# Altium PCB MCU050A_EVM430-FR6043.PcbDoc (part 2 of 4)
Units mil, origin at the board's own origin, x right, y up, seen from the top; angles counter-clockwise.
Board outline 6000 x 4000 mil, 4 copper layers (Top Layer, GND, PWR, Bottom Layer), stack 61.2 mil thick; 337 components, 255 nets, 1099 pads, 437 vias.
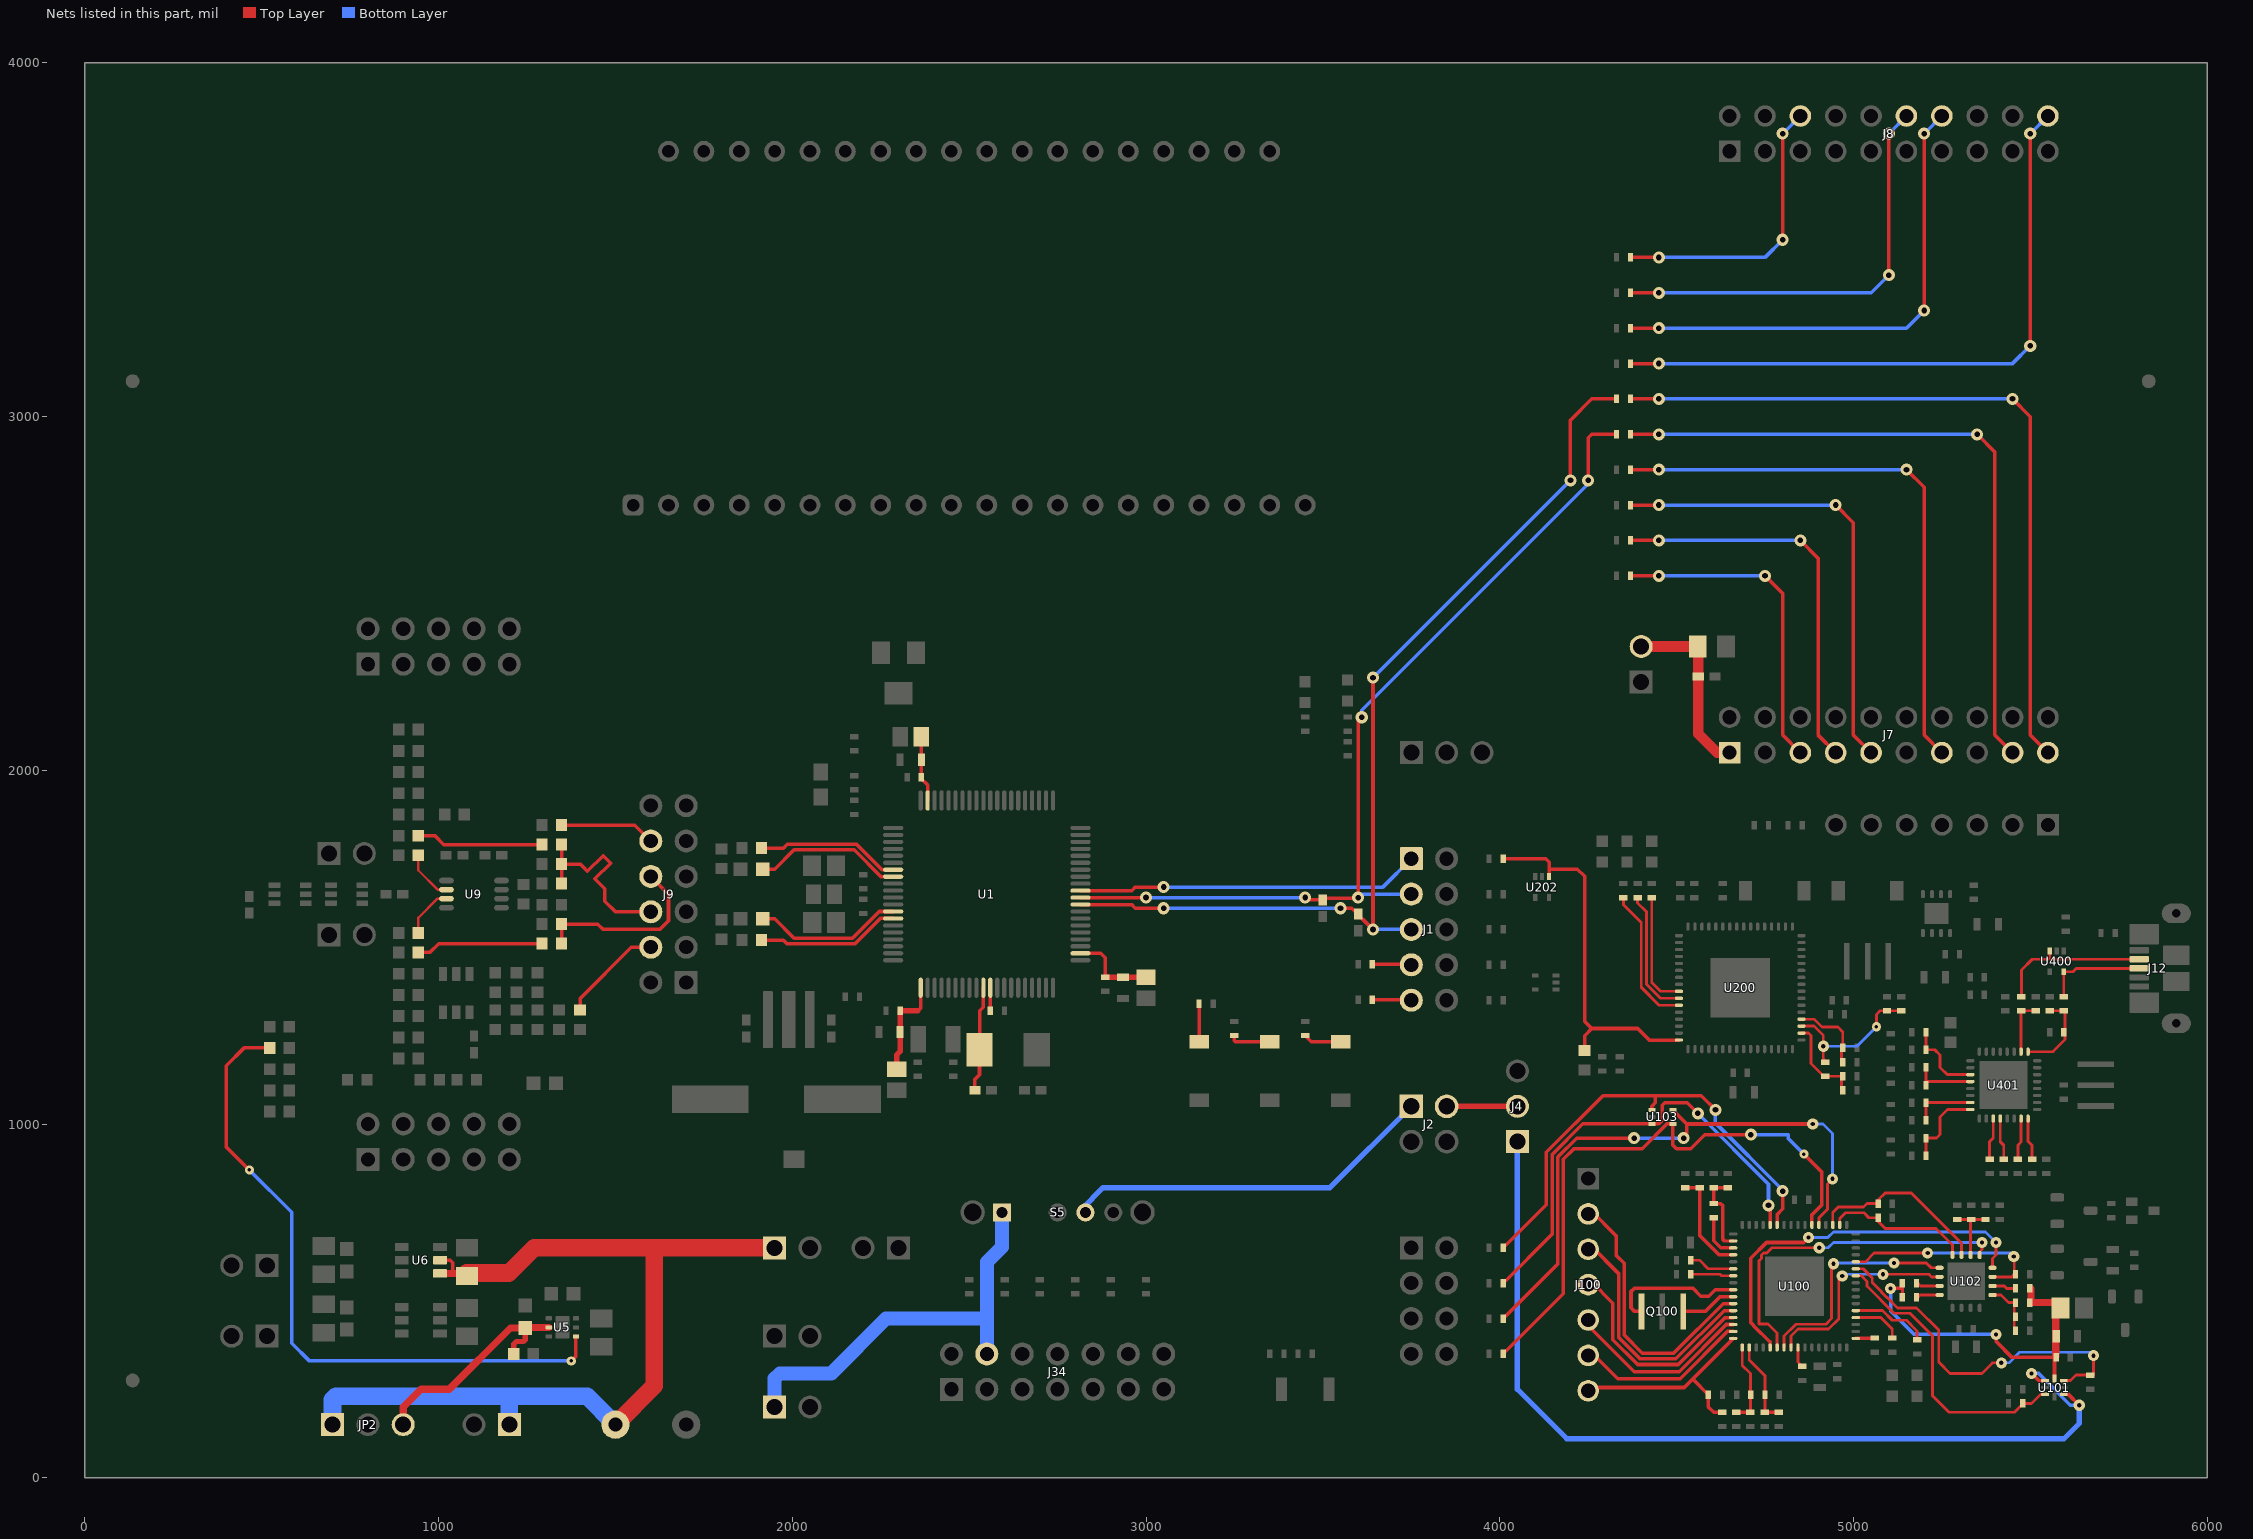
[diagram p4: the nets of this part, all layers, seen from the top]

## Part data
C1 C2 C3 C23 C33 C34 C37 C38 C41 C102 C104 C108 C113 C118 C119 C121 C202 C203 C204 C400 C402 C408 C409 C411: "CAP, CERM, 0.1 µF, 16 V, +/- 10%, X7R, 0402", Cap_Case=0402, Manufacturer=MuRata, Supplier Part Number 1=490-3261-1-ND, TempCo=X7R, Tolerance_%=10, Value1=Unknown, Value2=16V, ValueDisplayed=0.1µF
C4 C5 C17 C111 C210: "CAP, CERM, 1000 pF, 50 V, +/- 5%, C0G/NP0, 0402", Cap_Case=0402, Manufacturer=MuRata, Supplier Part Number 1=490-3244-1-ND, TempCo=C0G/NP0, Tolerance_%=5, Value1=Unknown, Value2=50V, ValueDisplayed=1000pF
C6 C7 C8: "CAP, CERM, 1 µF, 10 V, +/- 10%, X7R, 0603", Cap_Case=0603, Manufacturer=MuRata, Supplier Part Number 1=490-3899-1-ND, TempCo=X7R, Tolerance_%=10, Value1="0.011 ohm", Value2=10V, ValueDisplayed=1µF
C9 C10: library part CMP-0007824-2, "CAP, CERM, 33 uF, 10 V, +/- 20%, X5R, 0805", Cap_Case=0805, Manufacturer=TDK, Supplier Part Number 1=445-8238-1-ND, TempCo=X5R, Tolerance_%=20%, Value1="0.001694 ohm", Value2=10V, ValueDisplayed=33uF
C11 C12 C13 C14 C15 C16: "CAP, CERM, 12 pF, 50 V, +/- 5%, C0G/NP0, 0402", Cap_Case=0402, Manufacturer=MuRata, Supplier Part Number 1=81-GRM1555C1H120JA1D, TempCo=C0G/NP0, Tolerance_%=5, Value1=Unknown, Value2=50V, ValueDisplayed=12pF
C18 C103 C112 C116 C117 C120 C205: "CAP, CERM, 4.7 µF, 10 V, +/- 20%, X5R, 0603", Cap_Case=0603, Manufacturer=MuRata, TempCo=X5R, Tolerance_%=20, Value1=Unknown, Value2=10V, ValueDisplayed=4.7µF
C24: "CAP, CERM, 47 µF, 6.3 V, +/- 20%, X5R, 0805", Cap_Case=0805, Manufacturer=MuRata, Supplier Part Number 1=490-9960-1-ND, TempCo=X5R, Tolerance_%=20, Value1=Unknown, Value2=6.3V, ValueDisplayed=47µF
C25 C30: library part CMP-0008196-2, "CAP, CERM, 10 uF, 10 V, +/- 10%, X5R, 0805", Cap_Case=0805, Manufacturer=MuRata, Supplier Part Number 1=490-4735-1-ND, TempCo=X5R, Tolerance_%=10%, Value1="0.005 ohm", Value2=10V, ValueDisplayed=10uF
C27 C32: library part CMP-0008291-2, "CAP, CERM, 1 uF, 16 V, +/- 10%, X5R, 0805", Cap_Case=0805, Manufacturer=MuRata, Supplier Part Number 1=GRM21BR61C105KA01L-ND, TempCo=X5R, Tolerance_%=10%, Value1=Unknown, Value2=16V, ValueDisplayed=1uF
C28 C35 C45 C46: "CAP, CERM, 2.2 µF, 16 V, +/- 10%, X5R, 0603", Cap_Case=0603, Manufacturer=MuRata, Supplier Part Number 1=490-3296-1-ND, TempCo=X5R, Tolerance_%=10, Value1=Unknown, Value2=16V, ValueDisplayed=2.2µF
C29: "CAP, CERM, 4.7 µF, 16 V, +/- 10%, X5R, 0603", Cap_Case=0603, Manufacturer=MuRata, Supplier Part Number 1=490-10481-1-ND, TempCo=X5R, Tolerance_%=10, Value1=Unknown, Value2=16V, ValueDisplayed=4.7µF
C36 C40 C43: "CAP, CERM, 1 µF, 16 V, +/- 10%, X7R, 0603", Cap_Case=0603, Manufacturer=MuRata, Supplier Part Number 1=490-3900-1-ND, TempCo=X7R, Tolerance_%=10, Value1="0.011 ohm", Value2=16V, ValueDisplayed=1µF
C39: "CAP, CERM, 33 pF, 50 V, +/- 5%, C0G/NP0, 0603", Cap_Case=0603, Manufacturer=MuRata, Supplier Part Number 1=490-1415-1-ND, TempCo=C0G/NP0, Tolerance_%=5, Value1=Unknown, Value2=50V, ValueDisplayed=33pF
C42: "CAP, CERM, 1000 pF, 16 V,+/- 10%, X7R, 0603", Cap_Case=0603, Manufacturer=MuRata, Supplier Part Number 1=GRM188R71C102KA01D-ND, TempCo=X7R, Tolerance_%=10, Value2=16V, ValueDisplayed=1000pF
C44: "CAP, CERM, 680 pF, 50 V, +/- 5%, C0G/NP0, 0603", Cap_Case=0603, Manufacturer=MuRata, Supplier Part Number 1=490-1447-1-ND, TempCo=C0G/NP0, Tolerance_%=5, Value1=Unknown, Value2=50V, ValueDisplayed=680pF
C100 C101 C200 C201 C403 C404: "CAP, CERM, 22 pF, 50 V, +/- 5%, C0G/NP0, 0402", Cap_Case=0402, Manufacturer=MuRata, Supplier Part Number 1=81-GRM1555C1H220JA1D, TempCo=C0G/NP0, Tolerance_%=5, Value1=Unknown, Value2=50V, ValueDisplayed=22pF
C105 C106 C206 C207: "CAP, CERM, 0.22 µF, 16 V, +/- 10%, X7R, 0402", Cap_Case=0402, Manufacturer=MuRata, Supplier Part Number 1=490-5418-1-ND, TempCo=X7R, Tolerance_%=10, Value1=Unknown, Value2=16V, ValueDisplayed=0.22µF
C107 C208: "CAP, CERM, 0.47 µF, 16 V, +/- 10%, X5R, 0402", Cap_Case=0402, Manufacturer=MuRata, TempCo=X5R, Tolerance_%=10, Value1=Unknown, Value2=16V, ValueDisplayed=0.47µF
C109 C110 C114 C115: "CAP, CERM, 33 pF, 50 V, +/-5%, C0G/NP0, 0402", Cap_Case=0402, Manufacturer=MuRata, Supplier Part Number 1=81-GRM1555C1H330JA1D, TempCo=C0G/NP0, Tolerance_%=5, Value1=Unknown, Value2=50V, ValueDisplayed=33pF
C401 C405 C406 C407: "CAP, CERM, 10 pF, 50 V, +/- 5%, C0G/NP0, 0402", Cap_Case=0402, Manufacturer=MuRata, Supplier Part Number 1=81-GRM1555C1H100JA1D, TempCo=C0G/NP0, Tolerance_%=5, Value1=Unknown, Value2=50V, ValueDisplayed=10pF
C410 C413: "CAP, CERM, 10 µF, 10 V, +/- 20%, X5R, 0603", Cap_Case=0603, Manufacturer=MuRata, TempCo=X5R, Tolerance_%=20, Value1=Unknown, Value2=10V, ValueDisplayed=10µF
C412: "CAP, CERM, 0.01 µF, 16 V, +/- 10%, X7R, 0402", Cap_Case=0402, Manufacturer=MuRata, Supplier Part Number 1=490-1313-1-ND, TempCo=X7R, Tolerance_%=10, Value1=Unknown, Value2=16V, ValueDisplayed=0.01µF
D1 D2 LED102 LED201 LED202: "LED, Green, SMD", Color=green, Manufacturer=Lite-On, Supplier Part Number 1=160-1888-1-ND, Value1=W, Value2=3.2V
D102 D103: "Diode, Schottky, 40V, 0.2A, SOT-23", Manufacturer="Diodes Inc.", Supplier Part Number 1=BAS40-05DICT-ND, Value1=0.2A, Value2=0.9V
FB1 FB2: "Ferrite Bead, 220 ohm @ 100 MHz, 2.2 A, 0603", Alternate PartNumber=MPZ1608S221ATA00, Manufacturer=TDK, Supplier Part Number 1=445-1565-1-ND, Value1="0.05 ohm", Value2=2.2A
FID1 FID2 FID3: library part CMP-0077181-1, "Fiducial mark.  There is nothing to buy or mount.", Manufacturer=N/A
H1 H2 H3 H4: "Bumpon, Hemisphere, 0.44 X 0.20, Clear", Manufacturer=3M, Supplier Part Number 1=SJ5303-7-ND
J1 J10 J11: "Header, 100mil, 5x2, Gold, TH", Color=Black, Current_A=6.3, Manufacturer=Samtec, Supplier Part Number 1=SAM1028-05-ND, Voltage_V=550
J2: "Header, 2.54mm, 2x2, Gold, TH", Color=Black, Current_A=3, Manufacturer="Sullins Connector Solutions", Supplier Part Number 1=S2011E-02-ND, Voltage_V=1800
J3: "Header, 100mil, 4x2, Tin, TH", Color=Black, Current_A=3, Manufacturer="Sullins Connector Solutions", Supplier Part Number 1=S2012E-04-ND, Voltage_V=1800
J4 J13 JP2: "Header, 2.54 mm, 3x1, Gold, TH", Manufacturer="Wurth Elektronik", Supplier Part Number 1=732-5316-ND
J5 J6 J30 J31 J32 J33 JP1 JP3 JP4 JP5: "Header, 2.54 mm, 2x1, Gold, TH", Manufacturer="Wurth Elektronik", Supplier Part Number 1=732-5315-ND
J7 J8: library part CMP-0075628-1, "Header, 10x2, 2.54mm, Tin, TH", Color=Black, Manufacturer=Samtec, Supplier Part Number 1=SAM1034-10-ND, Voltage_V=550V
J9: library part CMP-0075412-1, "Header, 100mil, 6x2, Gold, TH", Color=Black, Current_A=6.3A, Manufacturer=Samtec, Supplier Part Number 1=SAM1028-06-ND, Voltage_V=550V
J12: "Receptacle, USB 2.0, Micro B, 5 Position, R/A, SMT", Color=Black, Current_A=1.8, Manufacturer=Molex, Supplier Part Number 1=WM11263CT-ND, Voltage_V=30
J34: "Header (shrouded), 100 mil, 7x2, Gold, TH", Manufacturer="Sullins Connector Solutions", Supplier Part Number 1=S9170-ND
J100 J200: "Header, 2.54 mm, 7x1, Gold, TH", Color=Black, Current_A=3, Manufacturer="Sullins Connector Solutions", Supplier Part Number 1=S1011E-07-ND, Voltage_V=1800
L1 L2 L3 L4: "Ferrite Bead, 600 ohm @ 100 MHz, 2 A, 0805", Alternate PartNumber=MPZ2012S601AT000, Manufacturer=TDK, Supplier Part Number 1=445-2206-1-ND, Value1="0.1 ohm", Value2=2A
L6: "Inductor, Multilayer, Ferrite, 1 µH, 0.8 A, 0.19 ohm, SMD", Manufacturer=MuRata, Supplier Part Number 1=490-4992-1-ND, Value1="0.19 ohm", Value2=0.8A, ValueDisplayed=1µH
L101: "Inductor, Shielded, Composite, 2.2uH, 0.95A, 0.16 ohm, SMD", Manufacturer=Samsung, Supplier Part Number 1=1276-6202-1-ND, Value1="0.16 ohm", Value2=0.95A, ValueDisplayed=2.2µH
LBL1: library part CMP-0003625-1, "Thermal Transfer Printable Labels, 0.650\" W x 0.200\" H - 10,000 per roll", Manufacturer=Brady, Supplier Part Number 1=97C5133
LCD: "108 Segment LCD Display, TH", Manufacturer="Adkom Elektronik"
LED101 LED203: "LED, Red, SMD", Color=red, Manufacturer=Lite-On, Power_TotalModule=0.0625, Supplier Part Number 1=160-1181-1-ND, Value1=0.0625W, Value2=2V
Logo1: library part TI_Logo, "Texas Instrument Corporate Signature"
Logo2: library part FCC_disclaimer, "FCC_disclaimer"
LOGO3: library part CMP-0074844-1
Logo4: library part CMP-0074769-1
NT1: "Single point connection between nets."
Q100 Q200: "Resonator, 4MHz, 39pF SMD", Frequency="4 MHz", Frequency Stability="±0.08 %", Manufacturer=MuRata
Q101: library part BSS84W-7-F, "MOSFET, P-CH, -50V, -0.13A, SOT-323", Alternate Manufacturer=None, Manufacturer="Diodes Inc.", Supplier Part Number 1=BSS84W-FDICT-ND, Value1="10 ohm", Value2="? nC"
Q102: library part "BC850CLT1G, ON Semiconductor", "Transistor, NPN, 45V, 0.1A, SOT-23", Manufacturer="ON Semiconductor", Supplier Part Number 1=BC850CLT1GOSCT-ND, Value1=0.1A, Value2=800
Q400: "Resonator, 6MHz, 15pF SMD", Frequency="6 MHz", Frequency Stability="±0.2 %", Manufacturer=MuRata, Supplier Part Number 1=490-1218-1-ND
R1 R9 R100 R101 R201 R203: "RES, 22, 5%, 0.063 W, 0402", Manufacturer=Vishay-Dale, Power_W=0.063, Supplier Part Number 1=541-22JCT-ND, TempCo="200 ppm/C", Tolerance_%=5, Value1=5%, Value2=0.063W, Value_Code=22R0, ValueDisplayed=22
R2 R121 R123: "RES, 47 k, 5%, 0.063 W, 0402", Manufacturer=Vishay-Dale, Power_W=0.063, Supplier Part Number 1=541-47KJCT-ND, TempCo="200 ppm/C", Tolerance_%=5, Value1=5%, Value2=0.063W, Value_Code=47k0, ValueDisplayed=47k
R3: "Trimmer, 200 K, 0.25 W, SMD", Manufacturer=Bourns, Supplier Part Number 1=3224W-1-204ECT-ND
R4 R5 R6: "RES, 330 k, 5%, 0.063 W, 0402", Manufacturer=Vishay-Dale, Power_W=0.063, Supplier Part Number 1=541-330KJCT-ND, TempCo="200 ppm/C", Tolerance_%=5, Value1=5%, Value2=0.063W, Value_Code=330k
R7 R8: "RES, 390, 5%, 0.063 W, 0402", Manufacturer=Vishay-Dale, Power_W=0.063, Supplier Part Number 1=541-390JCT-ND, TempCo="200 ppm/C", Tolerance_%=5, Value1=5%, Value2=0.063W, Value_Code=390R, ValueDisplayed=390
R10 R13 R14: library part CMP-0022899-2, "RES, 1.00 M, 1%, 0.1 W, 0603", Manufacturer="Yageo America", Power_W=100mW, Supplier Part Number 1=311-1.00MHRCT-ND, TempCo="200 ppm/C", Tolerance_%=1%, Value2=0.1W, Value_Code=1M00, ValueDisplayed=1.00M
R11 R12: "RES, 3.30 k, 1%, 0.1 W, AEC-Q200 Grade 0, 0402", Manufacturer=Panasonic, Power_W=0.1, Supplier Part Number 1=P3.30KLCT-ND, TempCo="100 ppm/C", Tolerance_%=1, Value1=1%, Value2=0.1W, Value_Code=3k30, ValueDisplayed=3.30k
R23 R46 R48 R50 R58 R64 R68 R69 R70 R71 R72 R73 R75 R76 R77 R78 R79 R80: "RES, 0, 5%, 0.1 W, 0603", Manufacturer="Yageo America", Power_W=0.1, Supplier Part Number 1=311-0.0GRCT-ND, TempCo="200 ppm/C", Tolerance_%=5, Value1=5%, Value2=0.1W, Value_Code=0000, ValueDisplayed=0
R26 R27 R28 R29 R30 R31 R32 R33 R34 R35 R36 R37 R38 R39 R40 R41 R52 R53 R54 R55 R56 R57 R124: "RES, 0, 5%, 0.063 W, 0402", Manufacturer=Vishay-Dale, Power_W=0.063, Supplier Part Number 1=541-0.0JCT-ND, TempCo="200 ppm/C", Tolerance_%=5, Value1=5%, Value2=0.063W, Value_Code=0000, ValueDisplayed=0
R42 R66: "RES, 24.9 k, 1%, 0.1 W, 0603", Manufacturer="Yageo America", Power_W=0.1, Supplier Part Number 1=311-24.9KHRCT-ND, TempCo="200 ppm/C", Tolerance_%=1, Value1=1%, Value2=0.1W, Value_Code=24k9, ValueDisplayed=24.9k
R43: "RES, 200 k, 1%, 0.1 W, 0603", Manufacturer="Yageo America", Power_W=0.1, Supplier Part Number 1=311-200KHRCT-ND, TempCo="200 ppm/C", Tolerance_%=1, Value1=1%, Value2=0.1W, Value_Code=200k
R44 R45 R65 R67: "RES, 2.00 M, 1%, 0.1 W, 0603", Manufacturer="Yageo America", Power_W=0.1, Supplier Part Number 1=311-2.00MHRCT-ND, TempCo="200 ppm/C", Tolerance_%=1, Value1=1%, Value2=0.1W, Value_Code=2M00, ValueDisplayed=2.00M
R47 R49 R51 R59: "RES, 806, 1%, 0.1 W, 0603", Manufacturer="Yageo America", Power_W=0.1, Supplier Part Number 1=311-806HRCT-ND, TempCo="200 ppm/C", Tolerance_%=1, Value1=1%, Value2=0.1W, Value_Code=806R, ValueDisplayed=806
R60: "RES, 10.0, 1%, 0.1 W, 0603", Manufacturer="Yageo America", Power_W=0.1, Supplier Part Number 1=311-10.0HRCT-ND, TempCo="200 ppm/C", Tolerance_%=1, Value1=1%, Value2=0.1W, Value_Code=10R0, ValueDisplayed=10.0
R61: "RES, 1.82 k, 1%, 0.1 W, 0603", Manufacturer="Yageo America", Power_W=0.1, Supplier Part Number 1=311-1.82KHRCT-ND, TempCo="200 ppm/C", Tolerance_%=1, Value1=1%, Value2=0.1W, Value_Code=1k82, ValueDisplayed=1.82k
R62 R207 R418: "RES, 10.0 k, 1%, 0.1 W, 0603", Manufacturer="Vishay Draloric", Power_W=0.1, Supplier Part Number 1=541-1784-1-ND, TempCo="100 ppm/C", Tolerance_%=1, Value1=1%, Value2=0.1W, Value_Code=10k0, ValueDisplayed=10.0k
R63: "RES, 499, 1%, 0.1 W, 0603", Manufacturer="Yageo America", Power_W=0.1, Supplier Part Number 1=311-499HRCT-ND, TempCo="200 ppm/C", Tolerance_%=1, Value1=1%, Value2=0.1W, Value_Code=499R, ValueDisplayed=499
R74: "RES, 0, 5%, 0.1 W, 0603", Manufacturer="Yageo America", Power_W=0.1, Supplier Part Number 1=311-0.0GRCT-ND, TempCo="200 ppm/C", Tolerance_%=5, Value1=5%, Value2=0.1W, Value_Code=0000, ValueDisplayed=DNI
R77 R78: library part CMP-0022902-3, "RES, 200, 1%, 0.1 W, 0603", Manufacturer="Yageo America", Power_W=100mW, Supplier Part Number 1=311-200HRCT-ND, TempCo="200 ppm/C", Tolerance_%=1%, Value2=0.1W, Value_Code=200R, ValueDisplayed=200
R81: "RES, 10.0 k, 1%, 0.1 W, 0603", Manufacturer="Vishay Draloric", Power_W=0.1, Supplier Part Number 1=541-1784-1-ND, TempCo="100 ppm/C", Tolerance_%=1, Value1=1%, Value2=0.1W, Value_Code=10k0, ValueDisplayed=0
R103 R206: "RES, 1.5 k, 5%, 0.063 W, 0402", Manufacturer=Vishay-Dale, Power_W=0.063, Supplier Part Number 1=71-CRCW0402J-1.5K-E3, TempCo="200 ppm/C", Tolerance_%=5, Value1=5%, Value2=0.063W, Value_Code=1k50, ValueDisplayed=1.5k
R104: "RES, 470, 5%, 0.063 W, 0402", Manufacturer=Vishay-Dale, Power_W=0.063, Supplier Part Number 1=541-470JCT-ND, TempCo="200 ppm/C", Tolerance_%=5, Value1=5%, Value2=0.063W, Value_Code=470R
R105 R202 R204: "RES, 390 ohm, 5%, 0.063W, 0402", Manufacturer=Vishay-Dale, Power_W=0.063, Supplier Part Number 1=541-390JCT-ND, TempCo="200 ppm/C", Tolerance_%=5, Value1=5%, Value2=0.063W, Value_Code=390R
R106 R209 R404: "RES, 47 k, 5%, 0.063 W, 0402", Manufacturer=Vishay-Dale, Power_W=0.063, Supplier Part Number 1=541-47KJCT-ND, TempCo="200 ppm/C", Tolerance_%=5, Value1=5%, Value2=0.063W, Value_Code=47k0
R107 R108 R116 R117 R118 R119: "RES, 221 k, 1%, 0.063 W, 0402", Manufacturer=Vishay-Dale, Power_W=0.063, Supplier Part Number 1=541-221KLCT-ND, TempCo="100 ppm/C", Tolerance_%=1, Value1=1%, Value2=0.063W, Value_Code=221k
R109: "RES, 150 k, 1%, 0.063 W, 0402", Manufacturer=Vishay-Dale, Power_W=0.063, Supplier Part Number 1=541-150KLCT-ND, TempCo="100 ppm/C", Tolerance_%=1, Value1=1%, Value2=0.063W, Value_Code=150k
R110: "RES, 240 k, 1%, 0.063 W, 0402", Manufacturer=Vishay-Dale, Power_W=0.063, Supplier Part Number 1=541-240KLCT-ND, TempCo="100 ppm/C", Tolerance_%=1, Value1=1%, Value2=0.063W, Value_Code=240k
R111 R112: "RES, 4.7 k, 5%, 0.063 W, 0402", Manufacturer=Vishay-Dale, Power_W=0.063, Supplier Part Number 1=541-4.7KJCT-ND, TempCo="200 ppm/C", Tolerance_%=5, Value1=5%, Value2=0.063W, Value_Code=4k70, ValueDisplayed=4.7k
R113 R200 R208: "RES, 2.20 k, 1%, 0.063 W, 0402", Manufacturer=Vishay-Dale, Power_W=0.063, Supplier Part Number 1=541-2.20KLCT-ND, TempCo="100 ppm/C", Tolerance_%=1, Value1=1%, Value2=0.063W, Value_Code=2k20, ValueDisplayed=2.20k
R114: "RES, 6.81 k, 1%, 0.063 W, 0402", Manufacturer=Vishay-Dale, Power_W=0.063, Supplier Part Number 1=541-6.81KLCT-ND, TempCo="100 ppm/C", Tolerance_%=1, Value1=1%, Value2=0.063W, Value_Code=6k81, ValueDisplayed=6.81k
R115: "RES, 3.32 k, 1%, 0.063 W, 0402", Manufacturer=Vishay-Dale, Power_W=0.063, Supplier Part Number 1=541-3.32KLCT-ND, TempCo="100 ppm/C", Tolerance_%=1, Value1=1%, Value2=0.063W, Value_Code=3k32, ValueDisplayed=3.32k
R120 R205: "RES, 470, 5%, 0.063 W, 0402", Manufacturer=Vishay-Dale, Power_W=0.063, Supplier Part Number 1=541-470JCT-ND, TempCo="200 ppm/C", Tolerance_%=5, Value1=5%, Value2=0.063W, Value_Code=470R, ValueDisplayed=470
R122: "RES, 820, 5%, 0.063 W, 0402", Manufacturer=Vishay-Dale, Power_W=0.063, Supplier Part Number 1=541-820JCT-ND, TempCo="200 ppm/C", Tolerance_%=5, Value1=5%, Value2=0.063W, Value_Code=820R, ValueDisplayed=820
R125 R126 R127 R128 R211 R212 R213 R214 R215 R216: "RES, 100, 5%, 0.063 W, 0402", Manufacturer=Vishay-Dale, Power_W=0.063, Supplier Part Number 1=541-100JCT-ND, TempCo="200 ppm/C", Tolerance_%=5, Value1=5%, Value2=0.063W, Value_Code=100R, ValueDisplayed=100
R210: "RES, 1.0 M, 5%, 0.063 W, 0402", Manufacturer=Vishay-Dale, Power_W=0.063, Supplier Part Number 1=541-1.0MJCT-ND, TempCo="200 ppm/C", Tolerance_%=5, Value1=5%, Value2=0.063W, Value_Code=1M00, ValueDisplayed=1.0M
R400 R401 R402 R403 R405 R410 R411 R412: "RES, 15 k, 5%, 0.063 W, 0402", Manufacturer=Vishay-Dale, Power_W=0.063, Supplier Part Number 1=541-15KJCT-ND, TempCo="200 ppm/C", Tolerance_%=5, Value1=5%, Value2=0.063W, Value_Code=15k0, ValueDisplayed=15k
R406: "RES, 27 ohm, 5%, 0.063W, 0402", Manufacturer=Vishay-Dale, Power_W=0.063, Supplier Part Number 1=541-27JCT-ND, TempCo="200 ppm/C", Tolerance_%=5, Value1=5%, Value2=0.063W, Value_Code=27R0
R407 R409 R413 R414 R415 R416: "RES, 22 ohm, 5%, 0.063W, 0402", Manufacturer=Vishay-Dale, Power_W=0.063, Supplier Part Number 1=541-22JCT-ND, TempCo="200 ppm/C", Tolerance_%=5, Value1=5%, Value2=0.063W, Value_Code=22R0
R408: "RES, 1.5 k, 5%, 0.063 W, 0402", Manufacturer=Vishay-Dale, Power_W=0.063, Supplier Part Number 1=541-1.5KJCT-ND, TempCo="200 ppm/C", Tolerance_%=5, Value1=5%, Value2=0.063W, Value_Code=1k50
RUSB: "RES, 33 ohm, 5%, 0.063W, 0402", Manufacturer=Vishay-Dale, Power_W=0.063, Supplier Part Number 1=541-33JCT-ND, TempCo="200 ppm/C", Tolerance_%=5, Value1=5%, Value2=0.063W, Value_Code=33R0
S1: "SWITCH TACTILE SPST-NO 0.05A 12V", CurrentRating_mA=50, Manufacturer="Omron Electronic Components", Supplier Part Number 1=SW1020CT-ND
S2 S3 S4 S201 S202: "Switch, Tactile, SPST-NO, 0.05A, 12V, SMT", CurrentRating_mA=50, Manufacturer=E-Switch, Supplier Part Number 1=EG4344CT-ND
S5: "Switch, Slide, SP3T, On-On-On, 3 Pos, 0.3A, 30 VDC, TH", CurrentRating_mA=300, Manufacturer="C&K Components", Supplier Part Number 1=CKN10371-ND
SH-J1 SH-J2 SH-J3 SH-J4 SH-J5 SH-J6 SH-J7 SH-J8 SH-J9 SH-J10 SH-J11 SH-J12 SH-J13 SH-J14 SH-J15 SH-J16 SH-J17 SH-J18: library part CMP-0003761-2, "Shunt, 2.54mm, Gold, Black", Manufacturer="Wurth Elektronik", Supplier Part Number 1=732-2678-ND
TP1: "Test Point, Miniature, Orange, TH", Manufacturer=Keystone, Supplier Part Number 1=36-5003-ND
TP2: "Test Point, Miniature, Black, TH", Manufacturer=Keystone, Supplier Part Number 1=36-5001-ND
U1: library part CMP-0074889-1, "Mixed-Signal Microcontroller, PN0080A (LQFP-80)", Alternate Manufacturer="Texas Instruments"
U4 U6: "Ultra-Low Leakage Load Switch, DBV0006A", Alternate Manufacturer="Texas Instruments", Supplier Part Number 1=296-43982-1-ND
U5: "3.5-MHz High Efficiency Step-Up Converter,  DRV0006A", Alternate Manufacturer="Texas Instruments", Alternate PartNumber=TPS61240DRVT, Supplier Part Number 1=296-24519-1-ND
U7 U8: "10-O SPDT ANALOG SWITCH SINGLE-CHANNEL 2:1 MULTIPLEXER/DEMULTIPLEXER, DCK0006A", Alternate Manufacturer="Texas Instruments", Alternate PartNumber=TS5A9411DCKT, Supplier Part Number 1=296-22731-1-ND
U9: "Dual-Bit Dual-Supply Bus Transceiver With Configurable Voltage Translation and 3-State Outputs, DCT0008A", Alternate Manufacturer="Texas Instruments", Alternate PartNumber=SN74LVC2T45DCTT, Supplier Part Number 1=296-16845-1-ND
U10: "Very Low Power, Rail to Rail Out, Negative Rail In, VFB Operational Amplifier, 2.5 to 5.5 V, -40 to 125 degC, 6-pin SOT23 (DBV6), Green (RoHS & no Sb/Br)", Alternate Manufacturer="Texas Instruments", Alternate PartNumber=Equivalent, Supplier Part Number 1=296-28761-1-ND
U100 U200: "Mixed Signal MicroController, RGC0064B", Alternate Manufacturer="Texas Instruments", Alternate PartNumber=MSP430F5528IRGCT, Frequency(MHz)=25, Supplier Part Number 1=296-27305-2-ND, Temp Sensor=Yes
U101: library part CMP-0074338-2, "0.75-Ohm DUAL SPST ANALOG SWITCH WITH 1.8-V COMPATIBLE INPUT LOGIC, RSE0008A (UQFN-8)", Alternate Manufacturer="Texas Instruments"
U102: library part CMP-0039612-1, "16 MHz Mixed Signal Microcontroller with 8 KB Flash, 256 B SRAM and 16 GPIOs, 16-pin QFN (RSA), Green (RoHS & no Sb/Br)", Frequency(MHz)=16, Manufacturer="Texas Instruments", Temp Sensor=Yes
U103 U201 U202: "Low-Capacitance Array with + / - 15 kV ESD Protection, 4 Channels, -40 to +85 degC, 5-pin SOT (DRL), Green (RoHS & no Sb/Br)", Alternate Manufacturer="Texas Instruments", Alternate PartNumber=Equivalent, Breakdown Voltage(Min)(V)=6, IO Capacitance(Typ)(pF)=11, IO Leakage Current(nA)=100, Supplier Part Number 1=296-25866-2-ND
U400: "Low-Capacitance + / - 15 kV ESD-Protection Array for High-Speed Data Interfaces, 2 Channels, -40 to +85 degC, 5-pin SOT (DRL), Green (RoHS & no Sb/Br)", Alternate Manufacturer=None, Alternate PartNumber=Equivalent, Breakdown Voltage(Min)(V)=11, IO Capacitance(Typ)(pF)=1.5, IO Leakage Current(nA)=1, Manufacturer="Texas Instruments", Supplier Part Number 1=296-21883-2-ND
U401: "4-Port Full-Speed USB Hub, 3.3V, -40 to 85 degC, 32-Pin QFN (RHB), Green (RoHS & no Sb/Br)", Alternate Manufacturer=None, Alternate PartNumber=Equivalent, Manufacturer="Texas Instruments", Supplier Part Number 1=296-21926-2-ND, Supply Voltage(s)(V)=3.3
U402: "Single Output High PSRR LDO, 500 mA, Fixed 3.3 V Output, 2.7 to 6.5 V Input, with Low IQ, 8-pin SON (DRB), -40 to 125 degC, Green (RoHS & no Sb/Br)", Alternate Manufacturer="Texas Instruments", Alternate PartNumber=Equivalent, Supplier Part Number 1=TPS73533DRBR-ND
Y1: "Crystal, 8MHz, SMD", Frequency=8MHz, Frequency Stability=±30ppm, Manufacturer="Abracon Corporation", Supplier Part Number 1=535-10630-1-ND
Y2: "CRYSTAL, 32.768KHZ, 9PF, SMD", Frequency=32.768kHz, Frequency Stability=±20ppm, Manufacturer="Abracon Corporation", Supplier Part Number 1=535-9544-1-ND
Y3: "Ceramic Resonator, 8MHz, 22pF, SMD", Frequency=8MHz, Manufacturer="Abracon Corporation", Supplier Part Number 1=535-10004-1-ND
Y4: library part CMP-0004580-3, "Crystal, 8 MHz, 18pF, SMD", Frequency_Fixed=8MHz, Frequency Stability=+/-50ppm, Manufacturer="Abracon Corporation", Supplier Part Number 1=535-10212-1-ND
ZZ1: library part AssemblyNoteLabel, Alternate Manufacturer=-
ZZ2 ZZ3 ZZ4: library part AssemblyNote, Alternate Manufacturer=-

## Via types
v1: diameter 26, hole 10, Top Layer to Bottom Layer, tented both sides, 173 vias
v2: diameter 34, hole 16, Top Layer to Bottom Layer, tented both sides, 142 vias
v3: diameter 31.5, hole 11.81, Top Layer to Bottom Layer, tented both sides, 56 vias
v4: diameter 19.68, hole 7.87, Top Layer to Bottom Layer, tented both sides, 35 vias
v5: diameter 50, hole 28, Top Layer to Bottom Layer, tented both sides, 23 vias
v6: diameter 19.68, hole 7.87, Top Layer to Bottom Layer, 7 vias
v7: diameter 34, hole 16, Top Layer to Bottom Layer, 1 vias

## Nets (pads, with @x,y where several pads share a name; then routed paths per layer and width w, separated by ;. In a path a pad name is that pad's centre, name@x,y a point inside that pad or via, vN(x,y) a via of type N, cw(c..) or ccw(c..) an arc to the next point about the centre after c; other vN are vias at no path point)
3V3: C30.1 JP1.1 JP2.1 JP3.1 TP1.1 U6.4 U6.5 | length 2576.4
  Top Layer w10: U6.5@1004.13,615 1032.67,615 1040,607.68 1040,577.6
  Top Layer w20: U6.4@1004.13,577.6 1040,577.6 C30.1@1079.09,577.6
  Top Layer w50: C30.1@1080,578.5 1198.5,578.5 1270,650 1610,650 ; TP1.1@1500,150 1610,260 1610,650 ; JP3.1@1950,650 1610,650
  Bottom Layer w50: JP2.1@700,150 700,220 710,230 1200,230 ; JP1.1@1200,150 1200,230 ; TP1.1@1500,150 1420,230 1200,230
+5V: C29.1 JP2.3 R23.1 U5.2 | length 653.5
  Top Layer w15: R23.1@1212.44,350 1212.44,377.44 1220,385 1240,385 1245,390 C29.1@1245,423.5
  Top Layer w20: JP2.3@900,150 900,200 950,250 1030,250 1203.5,423.5 C29.1@1245,423.5 1246.49,425 U5.2@1311.61,425
AFE_CH0_IN: C42.1 J9.4 | length 292.5
  Top Layer w10: C42.1@1400,1322.56 1400,1355 1545,1500 J9.4@1600,1500
AFE_CH0_OUT: J9.6 R14.2 R46.1 R50.1 | length 574.7
  Top Layer w10: R46.1@1347.56,1680 R14.2@1347.56,1735 ; R50.1@1347.56,1790 R14.2@1347.56,1735 ; J9.6@1600,1610 J9.6@1600,1600 1500,1600 1470,1630 1470,1665 1447.5,1687.5 1441.82,1693.18 1486.32,1737.68 1465.1,1758.89 1420.61,1714.39 1410,1725 1400,1735 R14.2@1347.56,1735
AFE_CH1_IN: J9.10 R10.2 | length 271.1
  Top Layer w10: R10.2@1347.56,1845 1555,1845 J9.10@1600,1800
AFE_CH1_OUT: J9.8 R13.2 R58.1 | length 519.7
  Top Layer w10: R58.1@1347.56,1510 R13.2@1347.56,1565 1450,1565 1465,1550 1625,1550 1650,1575 1650,1650 J9.8@1600,1700
AVCC1: C1.1 C6.1 L1.1 U1.1 | length 288.2
  Top Layer w10: 2355,1320 2362.99,1327.99 U1.1@2362.99,1385.24
  Top Layer w15: L1.1@2295,1154.53 2295,1195 2305,1205 C6.1@2305,1260 C1.1@2305,1320 2355,1320
BOOSTER_MTIF_OUT_IN: J7.9 R28.2 | length 1321.4
  Top Layer w10: R28.2@4370,2750 v2(4450,2750) ; v2(4950,2750) 5000,2700 5000,2100 J7.9@5050,2050
  Bottom Layer w10: v2(4450,2750) v2(4950,2750)
BOOSTER_MTIF_PIN_EN: J8.20 R35.2 | length 1821.4
  Top Layer w10: R35.2@4370,3150 v2(4450,3150) ; v2(5500,3200) v2(5500,3800)
  Bottom Layer w10: v2(4450,3150) 5450,3150 v2(5500,3200) ; v2(5500,3800) J8.20@5550,3850
BOOSTER_SCL: J7.17 R30.2 | length 1921.4
  Top Layer w10: R30.2@4370,2950 v2(4450,2950) ; v2(5350,2950) 5400,2900 5400,2100 J7.17@5450,2050
  Bottom Layer w10: v2(4450,2950) v2(5350,2950)
BOOSTER_SDA: J7.19 R31.2 | length 2121.4
  Top Layer w10: R31.2@4370,3050 v2(4450,3050) ; v2(5450,3050) 5500,3000 5500,2100 J7.19@5550,2050
  Bottom Layer w10: v2(4450,3050) v2(5450,3050)
BOOSTER_SPI_CLK: J7.13 R29.2 | length 1621.4
  Top Layer w10: R29.2@4370,2850 v2(4450,2850) ; v2(5150,2850) 5200,2800 5200,2100 J7.13@5250,2050
  Bottom Layer w10: v2(4450,2850) v2(5150,2850)
BOOSTER_SPI_CSN: J8.6 R32.2 | length 821.4
  Top Layer w10: R32.2@4370,3450 v2(4450,3450) ; v2(4800,3500) v2(4800,3800)
  Bottom Layer w10: v2(4450,3450) 4750,3450 v2(4800,3500) ; v2(4800,3800) J8.6@4850,3850
BOOSTER_SPI_MISO: J8.14 R34.2 | length 1421.4
  Top Layer w10: R34.2@4370,3250 v2(4450,3250) ; v2(5200,3300) v2(5200,3800)
  Bottom Layer w10: v2(4450,3250) 5150,3250 v2(5200,3300) ; v2(5200,3800) J8.14@5250,3850
BOOSTER_SPI_MOSI: J8.12 R33.2 | length 1221.4
  Top Layer w10: R33.2@4370,3350 v2(4450,3350) ; v2(5100,3400) v2(5100,3800)
  Bottom Layer w10: v2(4450,3350) 5050,3350 v2(5100,3400) ; v2(5100,3800) J8.12@5150,3850
BOOSTER_UART_RXD: J7.5 R26.2 | length 921.4
  Top Layer w10: R26.2@4370,2550 v2(4450,2550) ; v2(4750,2550) 4800,2500 4800,2100 J7.5@4850,2050
  Bottom Layer w10: v2(4450,2550) v2(4750,2550)
BOOSTER_UART_TXD: J7.7 R27.2 | length 1121.4
  Top Layer w10: R27.2@4370,2650 v2(4450,2650) ; v2(4850,2650) 4900,2600 4900,2100 J7.7@4950,2050
  Bottom Layer w10: v2(4450,2650) v2(4850,2650)
BOOSTER_VCC: C23.1 C24.1 J7.1 J30.2 | length 515.8
  Top Layer w30: J30.2@4400,2350 C24.1@4560,2350 ; C24.1@4561.38,2348.62 C23.1@4561.38,2265 4561.38,2103.62 4615,2050 J7.1@4650,2050
BUT_LEFT: R53.1 S2.2 | length 107.3
  Top Layer w10: S2.2@3150.01,1232.67 R53.1@3150,1340
BUT_RIGHT: R54.1 S4.2 | length 116
  Top Layer w10: R54.1@3250,1250 3250,1235 3252.33,1232.67 S4.2@3350.01,1232.67
BUT_SEL: R55.1 S3.2 | length 107.2
  Top Layer w10: R55.1@3450,1250 3467.33,1232.67 S3.2@3550.01,1232.67
CH0_IN: R75.1 U1.74 | length 407.1
  Top Layer w10: R75.1@1912.56,1520 1975,1520 1986,1509 2176.63,1509 2248.73,1581.1 U1.74@2285.24,1581.1
CH0_OUT: R77.1 U1.73 | length 426.9
  Top Layer w10: R77.1@1912.56,1580 1950,1580 2005,1525 2170,1525 2245.79,1600.79 U1.73@2285.24,1600.79
CH0_OUT_DRV: R50.2 R51.1 | length 360.2
  Top Layer w10: R51.1@942.56,1815 990,1815 1015,1790 R50.2@1292.44,1790
CH1_IN: R80.1 U1.67 | length 407.1
  Top Layer w10: R80.1@1912.56,1780 1916.5,1780 1975,1780 1986,1791 2181.63,1791 2253.73,1718.9 U1.67@2285.24,1718.9
CH1_OUT: R78.1 U1.68 | length 426.9
  Top Layer w10: R78.1@1912.56,1720 1950,1720 2005,1775 2175,1775 2250.79,1699.21 U1.68@2285.24,1699.21
CH1_OUT_DRV: R58.2 R59.1 | length 360.2
  Top Layer w10: R59.1@942.56,1485 975,1485 1000,1510 R58.2@1292.44,1510
COMM_IRQ: J1.1 U1.31 | length 972.6
  Top Layer w10: U1.31@2814.76,1659.84 2959.84,1659.84 2970,1670 v2(3050,1670)
  Bottom Layer w10: v2(3050,1670) 3670,1670 J1.1@3750,1750
COMM_RXD: J1.7 R56.1 | length 108.2
  Top Layer w10: R56.1@3640,1451.79 J1.7@3748.21,1451.79
COMM_SCL: J1.3 R11.1 R30.1 U1.30 | length 2634.4
  Top Layer w10: U1.30@2814.76,1640.16 v2(2999.84,1640.16) ; v2(3449.84,1640.16) 3456.38,1633.62 R11.1@3500,1633.62 3500,1638 3598,1638 v2(3600,1640) 3600,2150 v2(3610,2150) ; J1.3@3740.16,1640.16 J1.3@3750,1650 ; v2(4250,2820) 4250,2940 4260,2950 R30.1@4330,2950
  Bottom Layer w10: v2(2999.84,1640.16) v2(3449.84,1640.16) ; v2(3600,1640) 3610,1650 J1.3@3750,1650 J1.3@3740.16,1640.16 ; v2(3610,2150) 3610,2170 4250,2810 v2(4250,2820)
COMM_SDA: J1.5 R12.1 R31.1 U1.29 | length 2790.5
  Top Layer w10: U1.29@2814.76,1620.47 2959.53,1620.47 2970,1610 v2(3050,1610) ; v2(3550,1610) 3581.81,1610 v2(3641.81,1550) v2(3641.81,2261.81) ; v2(4200,2820) 4200,2990 4260,3050 R31.1@4330,3050
  Bottom Layer w10: v2(3050,1610) v2(3550,1610) ; v2(3641.81,1550) J1.5@3750,1550 ; v2(3641.81,2261.81) v2(4200,2820)
COMM_TXD: J1.9 R57.1 | length 110.7
  Top Layer w10: R57.1@3640,1351.79 3748.21,1351.79 J1.9@3750,1350
D+: J12.3 R407.1 U400.5 | length 284.4
  Top Layer w8: R407.1@5595,1363.62 5594.69,1363.94 U400.5@5594.69,1430.47 5620.47,1430.47 5630,1440 J12.3@5808.19,1440
D-: J12.2 R409.1 U400.3 | length 441.2
  Top Layer w8: R409.1@5475,1363.62 5475,1435 5505.59,1465.59 5555.32,1465.59 ; U400.3@5555.32,1489.53 5555.32,1465.59 ; J12.2@5808.19,1465.59 5555.32,1465.59
DCDC_ENA: R73.1 U5.4 | length 1890.4
  Top Layer w10: v1(465,870) 400,935 400,1165 450,1215 R73.1@522.44,1215 ; v1(1375,330) 1388.38,343.38 U5.4@1388.38,399.41
  Bottom Layer w10: v1(465,870) 585,750 585,379.99 635,330 v1(1375,330)
DM0: C404.1 R409.2 U401.2 | length 152.7
  Top Layer w8: U401.2@5474.21,1204.49 5474.21,1316.38 R409.2@5475,1316.38 ; R409.2@5475,1320 C404.1@5515,1320
DM1: C407.1 R414.2 U401.11 | length 225.2
  Top Layer w8: R414.2@5205,1260 C407.1@5205,1210 5230,1210 5245,1195 5245,1160 5265.47,1139.53 U401.11@5330.51,1139.53
DM2: C401.1 R415.2 U401.15 | length 175.5
  Top Layer w8: C401.1@5205,1010 R415.2@5205,1060 ; R415.2@5205,1060.79 U401.15@5330.51,1060.79
DM3: R401.1 U401.19 | length 116.2
  Top Layer w8: R401.1@5385,903.62 5385,950 5395.47,960.47 U401.19@5395.47,1015.51
DM4: R403.1 U401.23 | length 115.7
  Top Layer w8: R403.1@5465,903.62 5465,940 5474.21,949.21 U401.23@5474.21,1015.51
DP0: C403.1 R407.2 R408.1 U401.1 | length 241.7
  Top Layer w8: U401.1@5493.9,1204.49 5564.49,1204.49 5598.62,1238.62 5598.62,1312.76 5595,1316.38 R407.2@5595,1320 C403.1@5555,1320
DP1: C406.1 R413.2 U401.12 | length 172
  Top Layer w8: R413.2@5205,1110 C406.1@5205,1160 ; R413.2@5208.62,1120 5208.78,1119.84 U401.12@5330.51,1119.84
DP2: C405.1 R416.2 U401.16 | length 236.3
  Top Layer w8: R416.2@5205,910 5205,956.38 5208.62,960 5235,960 5245,970 5245,1020 5266.1,1041.1 U401.16@5330.51,1041.1
DP3: R400.1 U401.20 | length 116
  Top Layer w8: U401.20@5415.16,1015.51 5415.16,949.84 5425,940 R400.1@5425,903.62
DP4: R402.1 U401.24 | length 116.5
  Top Layer w8: U401.24@5493.9,1015.51 5493.9,951.1 5505,940 R402.1@5505,903.62
DRV1: R47.1 U9.2 | length 144.9
  Top Layer w7: R47.1@942.56,1760 942.56,1717.44 997.2,1662.8 U9.2@1022.24,1662.8
DRV2: R49.1 U9.3 | length 144.9
  Top Layer w7: R49.1@942.56,1540 942.56,1582.56 997.2,1637.2 U9.3@1022.24,1637.2
DVCC1: C2.2 C7.2 L3.1 U1.22 | length 245
  Top Layer w10: U1.22@2814.76,1482.68 2872.32,1482.68 2885,1470 C2.2@2885,1415
  Top Layer w15: C2.2@2885,1415 C7.2@2935,1415 L3.1@2999.53,1415
DVCC3: C3.1 C8.2 L4.1 U1.59 | length 187.1
  Top Layer w10: L4.1@2365,2094.53 C8.2@2365,2030 C3.1@2365,1980 2365,1976.06 2382.68,1958.38 U1.59@2382.68,1914.76
EXT_VCC: J33.1 J34.4 S5.1 | length 1168
  Bottom Layer w40: J33.1@1950,200 1950,280 1965,295 2110,295 2265,450 2550,450 ; J34.4@2550,350 2550,450 ; S5.1@2592.52,750 2592.52,652.52 2550,610 2550,450
EZ-FET_VCC: J2.1 S5.3 | length 1051.4
  Bottom Layer w15: S5.3@2818.74,760 2878.74,820 3520,820 J2.1@3750,1050
EZFET_AVBUS: C110.1 R109.2 R110.1 U100.1 | length 222.8
  Top Layer w8: U100.1@4685.87,368.17 4685.87,317.64 4709,294.5 C110.1@4709,185
  Top Layer w10: R109.2@4669,185 C110.1@4699,185
EZFET_AVCC: C115.1 R118.2 R119.2 U102.6 | length 180.2
  Top Layer w8: R118.2@5293.5,730 C115.1@5331.3,730 ; U102.6@5331.3,629.8 C115.1@5331.3,730 ; R119.2@5373.5,730 C115.1@5333.5,730 C115.1@5331.3,730
EZFET_AVCCOUT: C114.1 R116.1 R117.2 U102.1 | length 150.5
  Top Layer w8: U102.1@5393.31,516.61 5416.89,516.61 5438.5,495 5454.88,495 5454.88,455 C114.1@5454.88,415
EZFET_AVCCOUT2ADC: C109.1 R107.2 R108.1 U100.2 | length 236.7
  Top Layer w8: U100.2@4705.55,368.17 4705.55,332.95 4750.38,288.12 R107.2@4750.38,190
  Top Layer w10: R107.2@4749,185 C109.1@4789,185
EZFET_DCDCCAL0: R113.1 U102.12 | length 64.3
  Top Layer w8: R113.1@5182.13,510 5188.74,516.61 U102.12@5243.7,516.61
EZFET_DCDCCAL1: R115.2 U102.2 | length 64.6
  Top Layer w8: U102.2@5393.31,542.2 5426.3,542.2 5433.5,535 R115.2@5454.88,535
EZFET_DCDCCAL2: R114.1 U102.11 | length 64.8
  Top Layer w8: R114.1@5182.13,550 5189.92,542.2 U102.11@5243.7,542.2
EZFET_DCDCIO0: U100.5 U102.4 | length 1090.3
  Top Layer w8: U100.5@4764.61,368.17 4764.61,384.1 ; v3@4867,672 v3@4875,680 ; U102.4@5393.31,593.39 5393.31,619.8 5403.5,630 v3(5403.5,665)
  Top Layer w10: 4764.61,384.1 4763.19,384.1 4718.5,428.79 4718.5,430.2 4710,438.71 4710,620.57 4754.43,665 4860,665 v3@4867,672
  Bottom Layer w8: v3(4873.5,679.19) 4927.69,679.19 4943.5,695 5373.5,695 v3(5403.5,665)
EZFET_DCDCIO1: U100.6 U102.5 | length 975.8
  Top Layer w8: U100.6@4784.29,368.17 4784.29,409.21 4758.5,435 4733.5,435 4733.5,613.5 4739.84,619.84 4739.84,629.2 4745.7,635.06 4755.06,635.06 4770,650 v3(4903.5,650) ; U102.5@5356.89,629.8 5356.89,638.39 5363.5,645 v3(5363.5,665)
  Bottom Layer w8: v3(4903.5,650) 4928.5,650 4943.5,665 v3(5363.5,665)
EZFET_DCDCPULSE: R122.2 U100.28 U102.3 | length 576.3
  Top Layer w8: U100.28@5006.73,610.31 5033.81,610.31 5058.5,635 v3(5210,635) ; U102.3@5393.31,567.8 5447.68,567.8 5454.88,575 5454.88,623.62 v3(5453.5,625)
  Bottom Layer w8: v3(5210,635) 5443.5,635 v3(5453.5,625)
EZFET_DCDCRST: U100.7 U102.9 | length 651.3
  Top Layer w8: U100.7@4803.98,368.17 4803.98,400.27 4837.71,434 4922.5,434 4938.5,450 4938.5,600 v3(4943.5,605) ; v3(5115,607.38) 5206.13,607.38 5220.12,593.39 U102.9@5243.7,593.39
  Bottom Layer w8: v3(4943.5,605) 4945.88,607.38 v3(5115,607.38)
EZFET_DCDCTEST: U100.8 U102.10 | length 592.7
  Top Layer w8: U100.8@4823.66,368.17 4823.66,400.16 4843.5,420 4930,420 4958.5,448.5 4958.5,560 v3(4968.5,570) ; v3(5083.5,575) 5213.5,575 5220.71,567.8 U102.10@5243.7,567.8
  Bottom Layer w8: v3(4968.5,570) 4973.5,575 v3(5083.5,575)
EZFET_DM: C101.1 R101.2 U100.52 | length 293.1
  Top Layer w10: C101.1@4525,820 R101.2@4565,820 4565,685 4620,630 U100.52@4660.28,630
EZFET_DP: C100.1 R100.2 R103.2 U100.50 | length 240.8
  Top Layer w8: 4635.62,669.38 U100.50@4660.28,669.38 U100.50@4659.49,670.17
  Top Layer w10: 4635.62,669.38 4630,675 4630,770 4625,775 R103.2@4605,775 C100.1@4605,820 R100.2@4645,820
EZFET_HOSTSCL: R111.2 U100.35 U102.7 | length 519.7
  Top Layer w8: U100.35@4941.77,714.62 4941.77,749.66 4957.11,765 5028.5,765 5038.5,775 R111.2@5070,775 5070,785 5090,805 5163.5,805 5305.71,662.8 U102.7@5305.71,629.8
EZFET_HOSTSDA: R112.2 U100.34 U102.8 | length 415.6
  Top Layer w8: U100.34@4961.46,714.62 4961.46,732.95 4977.5,749 5029.5,749 5043.5,735 R112.2@5070,735 5070,725 5090,705 5233.5,705 5280.12,658.39 U102.8@5280.12,629.8
EZFET_LED1: R104.2 U100.20 | length 141.8
  Top Layer w8: U100.20@5006.73,452.79 5077.21,452.79 5110,420 R104.2@5110,395
EZFET_LED2: R105.2 U100.21 | length 222.1
  Top Layer w8: U100.21@5006.73,472.48 5082.52,472.48 5110,445 5150,445 5180,415 R105.2@5180,390
EZFET_PUR: R103.1 U100.51 | length 128.7
  Top Layer w10: R103.1@4605,735 4605,670 4625.31,649.69 U100.51@4660.28,649.69
EZFET_RST: C111.1 J100.7 R106.1 U100.64 | length 600.9
  Top Layer w10: J100.7@4258.5,255 4521.56,255 U100.64@4660.28,393.72 ; 4546.56,278.44 R106.1@4590,235 4590,200 4605,185 C111.1@4629,185
EZFET_SBWTCK_TST: R126.1 U100.44 U103.3 | length 1331.2
  Top Layer w10: R126.1@4010,550 4148,688 4148,913.25 4235.06,1000.32 U103.3@4430.47,1000.32 4450.31,1000.32 4460,1010 4460,1053.46 4466.54,1060 4530,1060 v2(4560,1030) ; v2(4760,770) 4764.61,765.39 U100.44@4764.61,714.62
  Bottom Layer w10: v2(4560,1030) 4760,830 v2(4760,770)
EZFET_SBWTDIO_RST: R125.1 U100.43 U103.1 | length 1336.2
  Top Layer w10: R125.1@4010,650 4132,772 4132,919.88 4292.12,1080 4440,1080 ; U103.1@4430.47,1039.69 4430.47,1050.47 4440,1060 4440,1080 ; v2(4610,1040) 4570,1080 4440,1080 ; U100.43@4784.29,714.62 4784.29,744.29 4800,760 v2(4800,810)
  Bottom Layer w10: v2(4610,1040) 4610,1002.63 4800,812.63 v2(4800,810)
EZFET_TARGET_VCC: J2.2 J4.2 | length 200
  Top Layer w15: J2.2@3850,1050 J4.2@4050,1050
EZFET_TCK: J100.6 U100.63 | length 488.1
  Top Layer w10: J100.6@4258.5,355 4333.5,280 4510,280 4643.41,413.41 U100.63@4660.28,413.41
EZFET_TDI: J100.4 U100.61 | length 614.7
  Top Layer w10: J100.4@4258.5,555 4320,493.5 4320,390 4390,320 4504.75,320 4637.54,452.79 U100.61@4660.28,452.79
EZFET_TDO: J100.3 U100.60 | length 696.4
  Top Layer w10: J100.3@4258.5,655 4336,577.5 4336,396.63 4396.63,336 4498.12,336 4634.6,472.48 U100.60@4660.28,472.48
EZFET_TEST: J100.2 U100.59 | length 778
  Top Layer w10: J100.2@4258.5,755 4330,683.5 4330,628.13 4352,606.13 4352,403.25 4403.25,352 4491.49,352 4631.66,492.17 U100.59@4660.28,492.17
EZFET_TMS: J100.5 U100.62 | length 540.7
  Top Layer w10: J100.5@4258.5,455 4258.5,421.5 4380,300 4507.37,300 4640.47,433.1 U100.62@4660.28,433.1
EZFET_UART_RXD: R128.1 U100.38 U103.4 | length 1684.3
  Top Layer w10: R128.1@4010,350 4180,520 4180,900 4210,930 4402.63,930 4472.94,1000.32 U103.4@4489.53,1000.32 4489.53,940.47 4500,930 4540,930 4580,970 v2(4710,970) ; v1(4860,915) 4910,865 4910,770 4882.72,742.72 U100.38@4882.72,714.62
  Bottom Layer w10: v2(4710,970) 4816.01,970 4816.01,958.99 v1(4860,915)
EZFET_UART_TXD: R127.1 U100.37 U103.5 | length 1683.1
  Top Layer w8: U100.37@4902.4,714.62 4902.4,735.01 4926.38,758.99 4926.38,830 v3(4941.38,845)
  Top Layer w10: R127.1@4010,450 4164,604 4164,906.63 4217.37,960 v2(4380,960) ; U103.5@4489.53,1039.69 4529.21,1000 ; v2@4529.21,969.21 4529.21,1000 ; v3(4885,1000) 4529.21,1000
  Bottom Layer w8: v3(4885,1000) 4914.06,1000 4941.38,972.69 v3(4941.38,845)
  Bottom Layer w10: v2(4380,960) v2(4520,960)
EZFET_V18: C106.1 U100.55 | length 118.3
  Top Layer w8: C106.1@4543.62,575 4622.55,575 4626.62,570.93 U100.55@4660.28,570.93
EZFET_VCCEN1: R123.2 U100.26 U101.3 | length 824.4
  Top Layer w8: U100.26@5006.73,570.93 5022.57,570.93 5038.5,555 5038.5,541.5 5115,465 5160,465 5223.5,401.5 5223.5,231.5 5270,185 5455,185 5480,210 5503.5,210 5528.82,235.32 U101.3@5542.91,235.32
EZFET_VCCEN2: R121.2 U100.27 U101.7 | length 1030
  Top Layer w8: U100.27@5006.73,590.62 5027.88,590.62 5053.5,565 5053.5,551.5 5079.25,525.75 5079.25,524.33 5094.33,509.25 5095.75,509.25 5125,480 5178.5,480 5241.38,417.13 5241.38,327.13 5273.5,295 5363.5,295 5393.26,324.75 v3(5418.26,324.75) ; U101.7@5594.09,274.68 5614.13,274.68 5629.44,290 R121.2@5670,290 5678.5,290 v3(5678.5,345)
  Bottom Layer w8: v3(5418.26,324.75) 5440.33,324.75 5470.08,354.5 5669,354.5 v3(5678.5,345)
EZFET_VCCOUT: C120.1 C121.1 L101.2 R113.2 R114.2 R115.1 R116.2 U101.8 | length 988.9
  Top Layer w8: R113.2@5138.5,510 5138.5,535 R114.2@5138.5,550
  Top Layer w10: v3(5105,535) 5138.5,535 ; v3(5403.5,405) 5403.5,385 5448.5,340 C121.1@5569.88,340
  Top Layer w12: U101.8@5568.5,280.59 C121.1@5568.5,338.62
  Top Layer w20: R115.1@5502.13,535 5502.13,495 5563.5,495 5578.5,480 5572.01,473.5 C121.1@5572.01,342.13
  Bottom Layer w10: v3(5105,535) 5105,472.06 5172.06,405 v3(5403.5,405)
EZFET_VCCTARGET: J4.1 U101.1 U101.5 | length 2693.1
  Top Layer w10: v3(5503.5,295) 5523.82,274.68 U101.1@5542.91,274.68 ; U101.5@5594.09,235.32 5608.19,235.32 v3(5638.5,205)
  Bottom Layer w10: v3(5503.5,295) 5523.5,295 5613.5,205 v3(5638.5,205)
  Bottom Layer w15: J4.1@4050,950 4050,250 4190,110 5595,110 5638.5,153.5 v3(5638.5,205)
EZFET_VCORE: C107.1 U100.17 | length 52
  Top Layer w10: U100.17@5006.73,393.72 C107.1@5058.72,393.72
EZFET_VREF: C108.1 U100.9 | length 58
  Top Layer w8: U100.9@4843.35,368.17 4843.35,326.65 C108.1@4855,315
EZFET_VUSB: C105.1 U100.54 | length 126.8
  Top Layer w8: C105.1@4543.62,615 4565,615 4589.38,590.62 U100.54@4660.28,590.62
EZFET_XT2IN: Q100.1 U100.57 | length 389.3
  Top Layer w10: Q100.1@4400.94,470 4381.26,470 4371.26,480 4371.26,526.26 4380,535 4547.17,535 4568.92,513.25 4591.08,513.25 4609.38,531.55 U100.57@4660.28,531.55
EZFET_XT2OUT: Q100.3 U100.58 | length 158.6
  Top Layer w10: Q100.3@4519.06,470 4580.81,470 4622.67,511.86 U100.58@4660.28,511.86
HFXIN: C16.1 U1.10 Y1.1 | length 300.1
  Top Layer w10: C16.1@2516.38,1095 2516.38,1126.38 2529.29,1139.29 Y1.1@2529.29,1210 2530,1210.71 2530,1320 2540.16,1330.16 U1.10@2540.16,1385.24
HFXOUT: R9.2 U1.11 | length 65.3
  Top Layer w10: U1.11@2559.84,1385.24 2559.84,1320.16 R9.2@2560,1320
HID-BRIDGE_DM: C200.1 R201.2 U200.52 | length 216.8
  Top Layer w8: U200.52@4853.23,1296.39 4888.6,1296.39 4911,1274 4956,1274 4970,1260 R201.2@4970,1215 ; C200.1@4966.38,1175 R201.2@4966.38,1215
HID-BRIDGE_DP: C201.1 R203.2 R206.1 U200.50 | length 253
  Top Layer w8: U200.50@4853.23,1257.01 4873.42,1257.01 4880,1250.43 4880,1171.38 4920,1131.38 4923.62,1135 4966.38,1135 R203.2@4966.38,1095
HID-BRIDGE_IRQ: R207.1 R212.1 U200.32 U202.1 | length 1052.5
  Top Layer w10: R212.1@4010,1750 4130,1750 4139.69,1740.31 U202.1@4139.69,1699.53 ; 4139.69,1720.31 4219.69,1720.31 4240,1700 4240,1290 4260,1270 ; R207.1@4240,1207.56 4240,1250 4260,1270 ; U200.32@4506.77,1237.32 4422.68,1237.32 4390,1270 4260,1270
HID-BRIDGE_LED3: R205.2 U200.25 | length 327.1
  Top Layer w8: R205.2@4430,1640 4430,1400 4454.85,1375.16 U200.25@4506.77,1375.16
HID-BRIDGE_LED4: R204.2 U200.26 | length 359.4
  Top Layer w8: R204.2@4390,1635.88 4390,1625 4415,1600 4415,1395 4454.53,1355.47 U200.26@4506.77,1355.47
HID-BRIDGE_LED5: R202.2 U200.27 | length 402
  Top Layer w8: R202.2@4350,1640 4350,1620 4400,1570 4400,1386.55 4450.77,1335.78 U200.27@4506.77,1335.78
HID-BRIDGE_PUR: R206.2 R210.2 R211.1 U200.51 | length 439.7
  Top Layer w8: U200.51@4853.23,1276.7 4888.3,1276.7 4915,1250 v3(4915,1220) 4915,1183.62 4920,1178.62 R206.2@4916.38,1175 ; v1(5065,1275) 5065,1310 5075,1320 R210.2@5095,1320 R211.1@5135,1320 R211.1@5141.38,1320
  Bottom Layer w8: v3(4915,1220) 5010,1220 v1(5065,1275)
